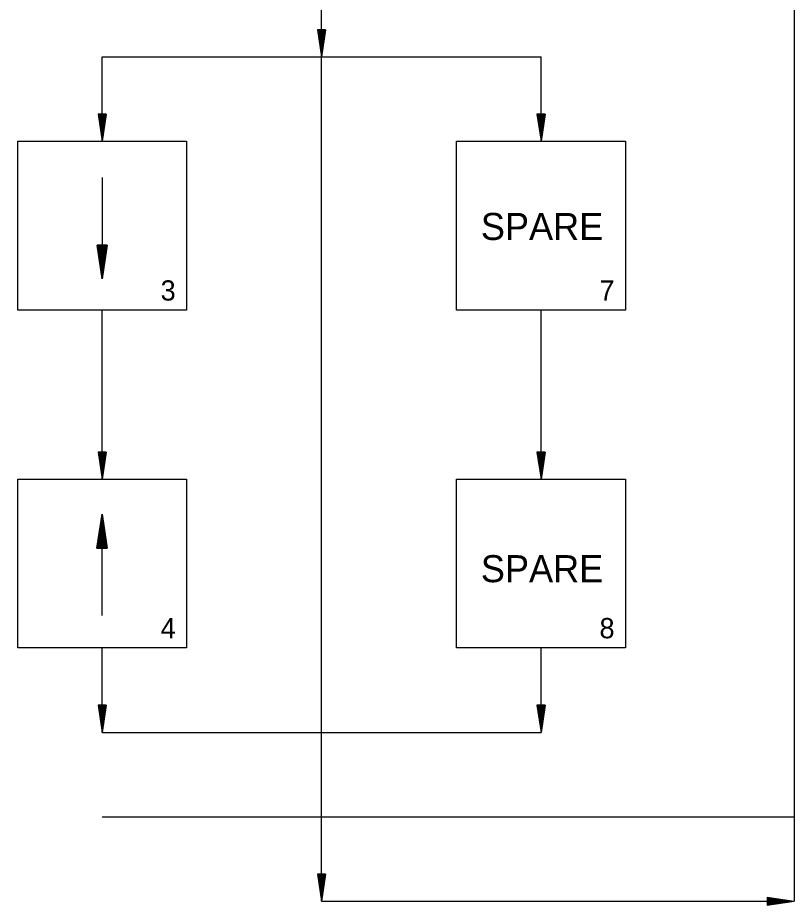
# Model space of a CAD drawing. Extents: x -218554 to 420114, y -565956 to -483460.
# Drawn here: x 418454.1 to 418507.4, y -565641 to -565580 of the extents above; entities that cross this region are included whole.
import ezdxf

# ---------------------------------------------------------------- set-up
doc = ezdxf.new("R2010")
doc.units = 0
doc.layers.add('Level 57', color=7, linetype='Continuous')

msp = doc.modelspace()

# ---------------------------------------------------------------- linework, layer by layer
at = {"layer": 'Level 57'}
for p, q in [((418474.944, -565640.702), (418474.944, -565518.953)), ((418507.41, -565518.953), (418507.41, -565640.702)), ((418474.666, -565580.871), (418474.944, -565582.726)), ((418475.222, -565580.871), (418474.666, -565580.871)), ((418474.712, -565580.871), (418474.944, -565582.416)), ((418474.759, -565580.871), (418474.944, -565582.097)), ((418474.806, -565580.871), (418474.944, -565581.788)), ((418474.853, -565580.871), (418474.944, -565581.474)), ((418474.9, -565580.871), (418474.944, -565581.164)), ((418475.222, -565580.871), (418474.944, -565582.726)), ((418475.034, -565580.871), (418474.944, -565581.474)), ((418475.128, -565580.871), (418474.944, -565582.097)), ((418475.176, -565580.871), (418474.944, -565582.416)), ((418475.082, -565580.871), (418474.944, -565581.788)), ((418474.987, -565580.871), (418474.944, -565581.164)), ((418459.87, -565582.726), (418490.017, -565582.726)), ((418459.87, -565588.524), (418459.87, -565582.726)), ((418490.017, -565588.524), (418490.017, -565582.726)), ((418459.592, -565586.668), (418459.87, -565588.524)), ((418460.148, -565586.668), (418459.592, -565586.668)), ((418459.638, -565586.668), (418459.87, -565588.214)), ((418459.686, -565586.668), (418459.87, -565587.895)), ((418459.732, -565586.668), (418459.87, -565587.586)), ((418459.779, -565586.668), (418459.87, -565587.271)), ((418459.827, -565586.668), (418459.87, -565586.962)), ((418460.148, -565586.668), (418459.87, -565588.524)), ((418459.96, -565586.668), (418459.87, -565587.271)), ((418460.055, -565586.668), (418459.87, -565587.895)), ((418460.102, -565586.668), (418459.87, -565588.214)), ((418460.008, -565586.668), (418459.87, -565587.586)), ((418459.914, -565586.668), (418459.87, -565586.962)), ((418489.739, -565586.668), (418490.017, -565588.524)), ((418490.296, -565586.668), (418489.739, -565586.668)), ((418489.786, -565586.668), (418490.017, -565588.214)), ((418489.833, -565586.668), (418490.017, -565587.895)), ((418489.879, -565586.668), (418490.017, -565587.586)), ((418489.927, -565586.668), (418490.017, -565587.271)), ((418489.974, -565586.668), (418490.017, -565586.962)), ((418490.296, -565586.668), (418490.017, -565588.524)), ((418490.107, -565586.668), (418490.017, -565587.271)), ((418490.202, -565586.668), (418490.017, -565587.895)), ((418490.249, -565586.668), (418490.017, -565588.214)), ((418490.156, -565586.668), (418490.017, -565587.586)), ((418490.061, -565586.668), (418490.017, -565586.962)), ((418459.87, -565591.006), (418459.87, -565597.963)), ((418459.87, -565597.963), (418459.522, -565595.644)), ((418460.218, -565595.644), (418459.522, -565595.644)), ((418459.58, -565595.644), (418459.87, -565597.575)), ((418459.87, -565597.177), (418459.639, -565595.644)), ((418459.697, -565595.644), (418459.87, -565596.79)), ((418459.87, -565596.397), (418459.756, -565595.644)), ((418459.815, -565595.644), (418459.87, -565596.01)), ((418459.87, -565596.01), (418459.924, -565595.644)), ((418459.982, -565595.644), (418459.87, -565596.397)), ((418459.87, -565596.79), (418460.043, -565595.644)), ((418460.101, -565595.644), (418459.87, -565597.177)), ((418459.87, -565597.575), (418460.16, -565595.644)), ((418460.218, -565595.644), (418459.87, -565597.963)), ((418459.87, -565611.714), (418459.87, -565600.119)), ((418490.017, -565611.714), (418490.017, -565600.119)), ((418459.592, -565609.859), (418459.87, -565611.714)), ((418460.148, -565609.859), (418459.592, -565609.859)), ((418459.638, -565609.859), (418459.87, -565611.404)), ((418459.686, -565609.859), (418459.87, -565611.085)), ((418459.732, -565609.859), (418459.87, -565610.776)), ((418459.779, -565609.859), (418459.87, -565610.462)), ((418459.827, -565609.859), (418459.87, -565610.152)), ((418460.148, -565609.859), (418459.87, -565611.714)), ((418459.96, -565609.859), (418459.87, -565610.462)), ((418460.055, -565609.859), (418459.87, -565611.085)), ((418460.102, -565609.859), (418459.87, -565611.404)), ((418460.008, -565609.859), (418459.87, -565610.776)), ((418459.914, -565609.859), (418459.87, -565610.152)), ((418489.739, -565609.859), (418490.017, -565611.714)), ((418490.296, -565609.859), (418489.739, -565609.859)), ((418489.786, -565609.859), (418490.017, -565611.404)), ((418489.833, -565609.859), (418490.017, -565611.085)), ((418489.879, -565609.859), (418490.017, -565610.776)), ((418489.927, -565609.859), (418490.017, -565610.462)), ((418489.974, -565609.859), (418490.017, -565610.152)), ((418490.296, -565609.859), (418490.017, -565611.714)), ((418490.107, -565609.859), (418490.017, -565610.462)), ((418490.202, -565609.859), (418490.017, -565611.085)), ((418490.249, -565609.859), (418490.017, -565611.404)), ((418490.156, -565609.859), (418490.017, -565610.776)), ((418490.061, -565609.859), (418490.017, -565610.152)), ((418459.515, -565616.455), (418459.863, -565614.136)), ((418459.863, -565621.093), (418459.863, -565614.136)), ((418459.863, -565614.136), (418460.211, -565616.455)), ((418459.863, -565614.523), (418459.573, -565616.455)), ((418459.632, -565616.455), (418459.863, -565614.922)), ((418460.153, -565616.455), (418459.863, -565614.523)), ((418459.863, -565614.922), (418460.094, -565616.455)), ((418459.863, -565615.308), (418459.69, -565616.455)), ((418460.036, -565616.455), (418459.863, -565615.308)), ((418459.751, -565616.455), (418459.863, -565615.701)), ((418459.863, -565616.088), (418459.808, -565616.455)), ((418459.863, -565615.701), (418459.977, -565616.455)), ((418459.917, -565616.455), (418459.863, -565616.088)), ((418459.515, -565616.455), (418460.211, -565616.455)), ((418459.87, -565629.107), (418459.87, -565623.309)), ((418490.017, -565629.107), (418490.017, -565623.309)), ((418459.592, -565627.251), (418459.87, -565629.107)), ((418460.148, -565627.251), (418459.592, -565627.251)), ((418459.638, -565627.251), (418459.87, -565628.797)), ((418459.686, -565627.251), (418459.87, -565628.478)), ((418459.732, -565627.251), (418459.87, -565628.169)), ((418459.779, -565627.251), (418459.87, -565627.854)), ((418459.827, -565627.251), (418459.87, -565627.545)), ((418460.148, -565627.251), (418459.87, -565629.107)), ((418459.96, -565627.251), (418459.87, -565627.854)), ((418460.055, -565627.251), (418459.87, -565628.478)), ((418460.102, -565627.251), (418459.87, -565628.797)), ((418460.008, -565627.251), (418459.87, -565628.169)), ((418459.914, -565627.251), (418459.87, -565627.545)), ((418489.739, -565627.251), (418490.017, -565629.107)), ((418490.296, -565627.251), (418489.739, -565627.251)), ((418489.786, -565627.251), (418490.017, -565628.797)), ((418489.833, -565627.251), (418490.017, -565628.478)), ((418489.879, -565627.251), (418490.017, -565628.169)), ((418489.927, -565627.251), (418490.017, -565627.854)), ((418489.974, -565627.251), (418490.017, -565627.545)), ((418490.296, -565627.251), (418490.017, -565629.107)), ((418490.107, -565627.251), (418490.017, -565627.854)), ((418490.202, -565627.251), (418490.017, -565628.478)), ((418490.249, -565627.251), (418490.017, -565628.797)), ((418490.156, -565627.251), (418490.017, -565628.169)), ((418490.061, -565627.251), (418490.017, -565627.545)), ((418459.87, -565629.107), (418490.017, -565629.107)), ((418459.87, -565634.904), (418507.41, -565634.904)), ((418474.666, -565638.847), (418474.944, -565640.702)), ((418475.222, -565638.847), (418474.666, -565638.847)), ((418474.712, -565638.847), (418474.944, -565640.392)), ((418474.759, -565638.847), (418474.944, -565640.073)), ((418474.806, -565638.847), (418474.944, -565639.764)), ((418474.853, -565638.847), (418474.944, -565639.45)), ((418474.9, -565638.847), (418474.944, -565639.14)), ((418475.222, -565638.847), (418474.944, -565640.702)), ((418475.034, -565638.847), (418474.944, -565639.45)), ((418475.128, -565638.847), (418474.944, -565640.073)), ((418475.176, -565638.847), (418474.944, -565640.392)), ((418475.082, -565638.847), (418474.944, -565639.764)), ((418474.987, -565638.847), (418474.944, -565639.14)), ((418505.555, -565640.423), (418507.41, -565640.702)), ((418505.555, -565640.423), (418505.555, -565640.98)), ((418505.555, -565640.47), (418507.1, -565640.702)), ((418505.555, -565640.517), (418506.781, -565640.702)), ((418505.555, -565640.564), (418506.472, -565640.702)), ((418505.555, -565640.612), (418506.158, -565640.702)), ((418505.555, -565640.658), (418505.848, -565640.702)), ((418474.944, -565640.702), (418507.41, -565640.702)), ((418505.555, -565640.98), (418507.41, -565640.702)), ((418505.555, -565640.793), (418506.158, -565640.702)), ((418505.555, -565640.886), (418506.781, -565640.702)), ((418505.555, -565640.934), (418507.1, -565640.702)), ((418505.555, -565640.84), (418506.472, -565640.702)), ((418505.555, -565640.745), (418505.848, -565640.702))]:
    msp.add_line(p, q, dxfattribs=at)
for points in [[(418454.073, -565588.524), (418465.668, -565588.524), (418465.668, -565600.119), (418454.073, -565600.119)], [(418484.22, -565588.524), (418495.815, -565588.524), (418495.815, -565600.119), (418484.22, -565600.119)], [(418454.073, -565611.714), (418465.668, -565611.714), (418465.668, -565623.309), (418454.073, -565623.309)], [(418484.22, -565611.714), (418495.815, -565611.714), (418495.815, -565623.309), (418484.22, -565623.309)]]:
    msp.add_lwpolyline(points, close=True, dxfattribs=at)

# ---------------------------------------------------------------- texts
for s, height, p in [('SPARE', 1.8552, (418485.882, -565595.298)), ('3', 1.391, (418463.885, -565599.459)), ('7', 1.391, (418494.032, -565599.459)), ('SPARE', 1.8552, (418485.882, -565618.796)), ('4', 1.391, (418463.885, -565622.649)), ('8', 1.391, (418494.032, -565622.649))]:
    msp.add_text(s, height=height, rotation=360, dxfattribs=at).set_placement(p)

doc.saveas('drawing.dxf')
